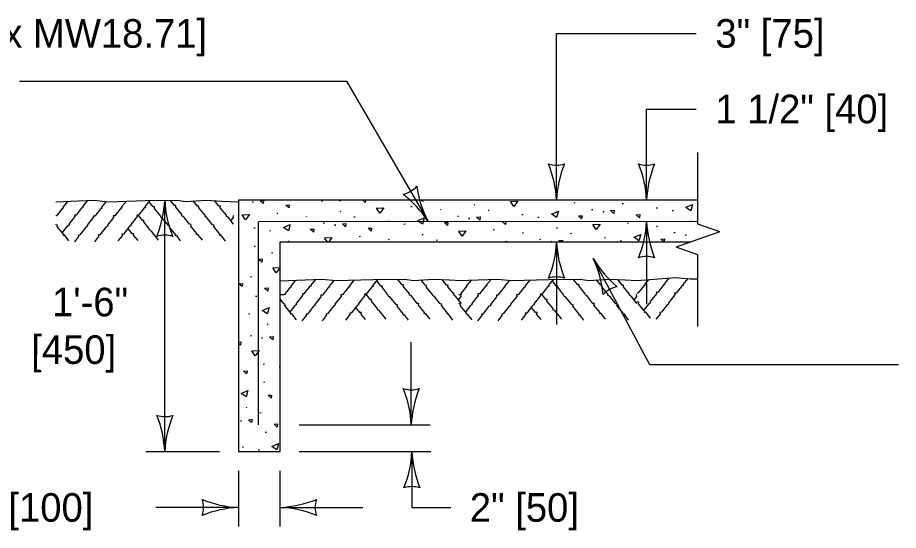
# Model space of a CAD drawing. Extents: x 49991.4 to 50021, y 49987.6 to 50011.4.
# Drawn here: x 50000.874 to 50002.724, y 49992.754 to 49993.83 of the extents above; entities that cross this region are included whole.
import ezdxf

# ---------------------------------------------------------------- set-up
doc = ezdxf.new("R2010")
doc.units = 0
for name, color, linetype in [('Level 1', 7, 'Continuous'), ('Level 2', 7, 'Continuous'), ('Level 3', 7, 'Continuous'), ('Level 6', 7, 'Continuous')]:
    doc.layers.add(name, color=color, linetype=linetype)

msp = doc.modelspace()

# ---------------------------------------------------------------- linework, layer by layer
at = {"layer": 'Level 1'}
for p, q in [((50002.3025, 49993.4474), (50001.3374, 49993.4474)), ((50001.3374, 49993.4474), (50001.3374, 49992.9196)), ((50001.3677, 49993.4446), (50001.3668, 49993.443)), ((50001.3677, 49993.4434), (50001.3668, 49993.4417)), ((50001.5118, 49993.4459), (50001.5144, 49993.4462)), ((50001.8343, 49993.4381), (50001.8325, 49993.4366)), ((50002.0436, 49993.4422), (50002.0428, 49993.4405)), ((50002.1434, 49993.4402), (50002.1461, 49993.4405)), ((50001.4179, 49993.4201), (50001.4205, 49993.4203)), ((50001.5527, 49993.424), (50001.5508, 49993.4226)), ((50001.6996, 49993.434), (50001.7022, 49993.4343)), ((50001.762, 49993.4281), (50001.7611, 49993.4264)), ((50001.8617, 49993.4262), (50001.8644, 49993.4264)), ((50002.079, 49993.4278), (50002.0815, 49993.4281)), ((50002.104, 49993.424), (50002.1033, 49993.4224)), ((50002.104, 49993.4228), (50002.1033, 49993.4212)), ((50002.2147, 49993.4312), (50002.2174, 49993.4314)), ((50002.2482, 49993.4254), (50002.2509, 49993.4256)), ((50002.3025, 49993.4028), (50001.3798, 49993.4022)), ((50001.3798, 49992.9758), (50001.3798, 49993.4022)), ((50001.4802, 49993.4141), (50001.4794, 49993.4124)), ((50001.58, 49993.4122), (50001.5826, 49993.4124)), ((50001.6513, 49993.4031), (50001.6539, 49993.4034)), ((50001.7973, 49993.4138), (50001.7999, 49993.4141)), ((50001.8224, 49993.41), (50001.8216, 49993.4083)), ((50001.8224, 49993.4087), (50001.8216, 49993.407)), ((50001.933, 49993.4171), (50001.9356, 49993.4173)), ((50001.9666, 49993.4114), (50001.9692, 49993.4116)), ((50002.2891, 49993.4035), (50002.2871, 49993.402)), ((50001.3696, 49993.389), (50001.3723, 49993.3893)), ((50001.4031, 49993.3832), (50001.4058, 49993.3834)), ((50001.5156, 49993.3997), (50001.5182, 49993.3999)), ((50001.5407, 49993.396), (50001.5399, 49993.3942)), ((50001.5407, 49993.3948), (50001.5399, 49993.3929)), ((50001.6848, 49993.3973), (50001.6875, 49993.3975)), ((50001.8726, 49993.3853), (50001.8752, 49993.3855)), ((50002.0074, 49993.3894), (50002.0054, 49993.388)), ((50002.1543, 49993.3994), (50002.157, 49993.3997)), ((50002.2166, 49993.3936), (50002.2158, 49993.3917)), ((50001.5909, 49993.3712), (50001.5935, 49993.3716)), ((50001.6533, 49993.3654), (50001.6524, 49993.3636)), ((50001.7258, 49993.3754), (50001.7237, 49993.374)), ((50001.753, 49993.3634), (50001.7557, 49993.3638)), ((50001.9349, 49993.3795), (50001.9341, 49993.3777)), ((50001.9703, 49993.3651), (50001.9728, 49993.3654)), ((50002.0348, 49993.3775), (50002.0374, 49993.3778)), ((50002.106, 49993.3684), (50002.1087, 49993.3687)), ((50002.1396, 49993.3626), (50002.1422, 49993.363)), ((50002.2519, 49993.3792), (50002.2545, 49993.3794)), ((50002.2771, 49993.3754), (50002.2761, 49993.3735)), ((50002.2771, 49993.3741), (50002.2763, 49993.3723)), ((50001.3716, 49993.3513), (50001.3707, 49993.3496)), ((50001.4252, 49992.9196), (50001.4252, 49993.3596)), ((50001.4252, 49993.3596), (50002.2875, 49993.3596)), ((50001.444, 49993.3613), (50001.4421, 49993.3599)), ((50001.9954, 49993.3613), (50001.9946, 49993.3596)), ((50001.9954, 49993.36), (50001.9952, 49993.3596)), ((50001.4069, 49993.337), (50001.4095, 49993.3372)), ((50001.3628, 49993.2866), (50001.3654, 49993.287)), ((50001.3736, 49993.2458), (50001.3763, 49993.246)), ((50001.3588, 49993.209), (50001.3613, 49993.2094)), ((50001.3996, 49993.1871), (50001.3976, 49993.1857)), ((50001.3624, 49993.1628), (50001.3652, 49993.163)), ((50001.3876, 49993.159), (50001.3868, 49993.1574)), ((50001.3876, 49993.1578), (50001.3868, 49993.156)), ((50001.3897, 49993.1034), (50001.3924, 49993.1037)), ((50001.4232, 49993.0976), (50001.4252, 49993.0978)), ((50001.3917, 49993.0658), (50001.3907, 49993.064)), ((50001.3554, 49993.013), (50001.3534, 49993.0115)), ((50001.3827, 49993.001), (50001.3853, 49993.0014)), ((50001.3434, 49992.9849), (50001.3425, 49992.9832)), ((50001.3434, 49992.9836), (50001.3425, 49992.9819)), ((50001.3936, 49992.9603), (50001.3962, 49992.9605)), ((50001.3374, 49992.9196), (50001.4252, 49992.9196)), ((50001.3453, 49992.9292), (50001.3479, 49992.9295)), ((50001.3788, 49992.9234), (50001.3815, 49992.9236))]:
    msp.add_line(p, q, dxfattribs=at)
for points in [[(50000.9537, 49993.4442), (50001.0341, 49993.4475), (50001.0647, 49993.4442), (50001.1425, 49993.447), (50001.2082, 49993.4474), (50001.2268, 49993.4447), (50001.2694, 49993.4477), (50001.3024, 49993.4456), (50001.3374, 49993.4436)], [(50000.9793, 49993.4453), (50000.9692, 49993.4333), (50000.9704, 49993.4305), (50000.9682, 49993.4305), (50000.9553, 49993.4144), (50000.9537, 49993.4144)], [(50001.0205, 49993.4469), (50001.011, 49993.4349), (50001.0124, 49993.4324), (50001.0096, 49993.4324), (50000.9969, 49993.416), (50000.9935, 49993.416), (50000.9939, 49993.4132), (50000.9811, 49993.3969), (50000.9811, 49993.3936), (50000.978, 49993.3925), (50000.9676, 49993.3793)], [(50001.0592, 49993.4442), (50001.0497, 49993.4325), (50001.0507, 49993.4301), (50001.0484, 49993.4301), (50001.0357, 49993.4138), (50001.0324, 49993.4138), (50001.0326, 49993.4107), (50001.0198, 49993.3946), (50001.0198, 49993.3914), (50001.0168, 49993.3905), (50001.0045, 49993.3743), (50001.0013, 49993.3738), (50001.0016, 49993.371), (50000.9929, 49993.3598)], [(50001.1023, 49993.4455), (50001.092, 49993.4333), (50001.0929, 49993.4305), (50001.0907, 49993.4305), (50001.078, 49993.4144), (50001.0747, 49993.4144), (50001.0748, 49993.411), (50001.0624, 49993.3949), (50001.0624, 49993.3922), (50001.0588, 49993.3909), (50001.0464, 49993.3748), (50001.0434, 49993.3744), (50001.0438, 49993.3712), (50001.0352, 49993.3602)], [(50001.1513, 49993.447), (50001.1417, 49993.4349), (50001.1425, 49993.4322), (50001.1403, 49993.4322), (50001.1275, 49993.416), (50001.1242, 49993.416), (50001.1247, 49993.413), (50001.1114, 49993.3963), (50001.1114, 49993.3934), (50001.1086, 49993.3925), (50001.096, 49993.3762), (50001.0929, 49993.3758), (50001.0937, 49993.373), (50001.0845, 49993.3617)], [(50001.2159, 49993.3617), (50001.2078, 49993.3729), (50001.2051, 49993.3728), (50001.2057, 49993.3744), (50001.1928, 49993.3906), (50001.1937, 49993.3936), (50001.1904, 49993.3944), (50001.1774, 49993.4106), (50001.1746, 49993.411), (50001.1743, 49993.4139), (50001.1614, 49993.4301), (50001.1615, 49993.4333), (50001.1585, 49993.4333), (50001.1495, 49993.4448)], [(50001.2618, 49993.3632), (50001.2521, 49993.3754), (50001.2497, 49993.3749), (50001.2502, 49993.3771), (50001.2372, 49993.3931), (50001.2384, 49993.3963), (50001.2347, 49993.3969), (50001.2221, 49993.4134), (50001.2189, 49993.4138), (50001.2189, 49993.417), (50001.2057, 49993.4328), (50001.2062, 49993.4359), (50001.2029, 49993.4359), (50001.194, 49993.4473)], [(50001.3102, 49993.3616), (50001.3007, 49993.3743), (50001.2982, 49993.3735), (50001.2984, 49993.3758), (50001.2855, 49993.3922), (50001.2868, 49993.3951), (50001.2833, 49993.3958), (50001.2702, 49993.4118), (50001.2674, 49993.4129), (50001.2674, 49993.4158), (50001.2541, 49993.4314), (50001.2546, 49993.4349), (50001.2517, 49993.4349), (50001.2424, 49993.4457)], [(50001.3274, 49993.3969), (50001.3157, 49993.412), (50001.3124, 49993.413), (50001.3122, 49993.416), (50001.2991, 49993.4316), (50001.2995, 49993.4349), (50001.2964, 49993.4349), (50001.2875, 49993.4465)], [(50001.3829, 49993.4462), (50001.3903, 49993.4469), (50001.3895, 49993.4401), (50001.3829, 49993.4462)], [(50001.4368, 49993.437), (50001.4442, 49993.4376), (50001.4434, 49993.431), (50001.4368, 49993.437)], [(50001.5516, 49993.4474), (50001.5511, 49993.4456), (50001.5486, 49993.4474)], [(50001.6041, 49993.4474), (50001.6037, 49993.4428), (50001.5987, 49993.4474)], [(50001.7253, 49993.4474), (50001.7251, 49993.4449), (50001.7225, 49993.4474)], [(50001.9087, 49993.4448), (50001.9242, 49993.4455), (50001.9161, 49993.4343), (50001.9088, 49993.4447)], [(50002.2769, 49993.4324), (50002.2913, 49993.4383), (50002.2874, 49993.425), (50002.2771, 49993.4323)], [(50001.627, 49993.4308), (50001.6425, 49993.4314), (50001.6344, 49993.4203), (50001.6271, 49993.4305)], [(50001.9952, 49993.4183), (50002.0096, 49993.4242), (50002.0057, 49993.4109), (50001.9954, 49993.4182)], [(50002.1192, 49993.4257), (50002.1267, 49993.4262), (50002.1258, 49993.4195), (50002.1192, 49993.4257)], [(50001.1698, 49993.3636), (50001.1548, 49993.3821), (50001.1521, 49993.3828), (50001.1513, 49993.3856), (50001.1387, 49993.4017), (50001.1389, 49993.4048), (50001.1358, 49993.4049), (50001.1274, 49993.416)], [(50001.3274, 49993.4144), (50001.3261, 49993.4144), (50001.3266, 49993.411), (50001.3212, 49993.405)], [(50001.3453, 49993.4168), (50001.3608, 49993.4173), (50001.3526, 49993.4062), (50001.3454, 49993.4166)], [(50001.7136, 49993.4043), (50001.7278, 49993.4101), (50001.7241, 49993.397), (50001.7138, 49993.4042)], [(50001.77, 49993.4002), (50001.7774, 49993.4008), (50001.7767, 49993.3941), (50001.77, 49993.4002)], [(50001.8375, 49993.4117), (50001.845, 49993.4122), (50001.8442, 49993.4056), (50001.8375, 49993.4117)], [(50001.8915, 49993.4024), (50001.8989, 49993.403), (50001.8981, 49993.3963), (50001.8915, 49993.4024)], [(50002.0517, 49993.4142), (50002.0591, 49993.4148), (50002.0582, 49993.4082), (50002.0517, 49993.4142)], [(50002.1731, 49993.4164), (50002.1806, 49993.417), (50002.1797, 49993.4104), (50002.1731, 49993.4164)], [(50000.9813, 49993.3621), (50000.9723, 49993.3744), (50000.9692, 49993.3735), (50000.9698, 49993.3762), (50000.9571, 49993.3924), (50000.9578, 49993.3951), (50000.9547, 49993.3958), (50000.9537, 49993.3969)], [(50001.1268, 49993.3626), (50001.1172, 49993.3738), (50001.1176, 49993.377), (50001.1144, 49993.377), (50001.1055, 49993.3887)], [(50001.4318, 49993.3903), (50001.4462, 49993.3961), (50001.4425, 49993.3828), (50001.4321, 49993.3902)], [(50001.4883, 49993.3862), (50001.4958, 49993.3867), (50001.495, 49993.3801), (50001.4883, 49993.3862)], [(50001.5558, 49993.3975), (50001.5633, 49993.3982), (50001.5625, 49993.3915), (50001.5558, 49993.3975)], [(50001.6098, 49993.3883), (50001.6172, 49993.3889), (50001.6164, 49993.3821), (50001.6098, 49993.3883)], [(50001.7999, 49993.3821), (50001.8154, 49993.3828), (50001.8073, 49993.3716), (50001.8001, 49993.3819)], [(50002.0816, 49993.3962), (50002.097, 49993.3969), (50002.089, 49993.3855), (50002.0817, 49993.396)], [(50001.5183, 49993.3682), (50001.5338, 49993.3687), (50001.5272, 49993.3596)], [(50001.5242, 49993.3596), (50001.5184, 49993.3679)], [(50002.0106, 49993.363), (50002.018, 49993.3635), (50002.0176, 49993.3596)], [(50002.0143, 49993.3596), (50002.0106, 49993.363)], [(50002.1682, 49993.3697), (50002.1826, 49993.3755), (50002.1787, 49993.3622), (50002.1685, 49993.3695)], [(50002.2247, 49993.3656), (50002.2321, 49993.3662), (50002.2312, 49993.3596)], [(50002.2311, 49993.3596), (50002.2247, 49993.3656)], [(50001.896, 49993.3596), (50001.9009, 49993.3614), (50001.9003, 49993.3596)], [(50001.3374, 49993.3333), (50001.3376, 49993.3334), (50001.3374, 49993.3325)], [(50001.3797, 49993.3235), (50001.3871, 49993.3239), (50001.3863, 49993.3173), (50001.3797, 49993.3235)], [(50001.4095, 49993.3053), (50001.425, 49993.3059), (50001.4169, 49993.2948), (50001.4097, 49993.3051)], [(50001.3386, 49993.272), (50001.346, 49993.2727), (50001.3452, 49993.266), (50001.3386, 49993.272)], [(50001.4252, 49993.2783), (50001.5127, 49993.2817), (50001.5427, 49993.2786), (50001.6207, 49993.2807), (50001.6865, 49993.2814), (50001.7048, 49993.2787), (50001.7475, 49993.2817), (50001.7804, 49993.2799), (50001.8058, 49993.2786)], [(50001.4575, 49993.2793), (50001.4474, 49993.2672), (50001.4484, 49993.2645), (50001.4462, 49993.2645), (50001.4333, 49993.2487), (50001.4252, 49993.2487)], [(50001.4992, 49993.2812), (50001.4893, 49993.2689), (50001.4899, 49993.2666), (50001.4877, 49993.2666), (50001.4751, 49993.2506), (50001.4719, 49993.2506), (50001.472, 49993.2476), (50001.459, 49993.2306), (50001.459, 49993.2278), (50001.456, 49993.2266), (50001.4459, 49993.2134)], [(50001.5373, 49993.2781), (50001.5278, 49993.2668), (50001.5289, 49993.2645), (50001.5263, 49993.2645), (50001.5138, 49993.2479), (50001.5106, 49993.2479), (50001.5108, 49993.2446), (50001.4978, 49993.2286), (50001.4978, 49993.2255), (50001.4949, 49993.2246), (50001.4826, 49993.2082), (50001.4794, 49993.2082), (50001.4797, 49993.2052), (50001.4708, 49993.194)], [(50001.5799, 49993.2793), (50001.5701, 49993.2672), (50001.5713, 49993.2645), (50001.5686, 49993.2645), (50001.5558, 49993.2487), (50001.5528, 49993.2487), (50001.553, 49993.2455), (50001.5401, 49993.229), (50001.5401, 49993.226), (50001.5371, 49993.2248), (50001.5246, 49993.2088), (50001.5217, 49993.2084), (50001.5218, 49993.2055), (50001.5132, 49993.1941)], [(50001.6297, 49993.2807), (50001.6197, 49993.2687), (50001.6206, 49993.266), (50001.6184, 49993.266), (50001.6055, 49993.2503), (50001.6024, 49993.2503), (50001.6028, 49993.2474), (50001.5898, 49993.2304), (50001.5898, 49993.2276), (50001.5868, 49993.2266), (50001.5742, 49993.2101), (50001.5713, 49993.21), (50001.5715, 49993.2071), (50001.5625, 49993.1956)], [(50001.6944, 49993.1956), (50001.6863, 49993.2068), (50001.6834, 49993.2061), (50001.6842, 49993.2084), (50001.6705, 49993.2247), (50001.6718, 49993.2278), (50001.6687, 49993.2283), (50001.6555, 49993.2445), (50001.6528, 49993.2454), (50001.6522, 49993.2481), (50001.6394, 49993.2645), (50001.6398, 49993.2672), (50001.6367, 49993.2672), (50001.6282, 49993.2787)], [(50001.74, 49993.1973), (50001.7302, 49993.2094), (50001.7278, 49993.2089), (50001.7283, 49993.2113), (50001.7153, 49993.227), (50001.7161, 49993.2304), (50001.7131, 49993.2306), (50001.7001, 49993.2476), (50001.697, 49993.2479), (50001.6967, 49993.2509), (50001.6837, 49993.2668), (50001.6842, 49993.27), (50001.681, 49993.27), (50001.6724, 49993.2812)], [(50001.7881, 49993.1956), (50001.7787, 49993.2082), (50001.7765, 49993.2078), (50001.7766, 49993.2099), (50001.7637, 49993.226), (50001.7644, 49993.2292), (50001.7614, 49993.2296), (50001.7485, 49993.2458), (50001.7456, 49993.2469), (50001.745, 49993.2496), (50001.7321, 49993.2655), (50001.7326, 49993.2684), (50001.7296, 49993.2687), (50001.721, 49993.28)], [(50001.8058, 49993.2306), (50001.7937, 49993.246), (50001.7906, 49993.247), (50001.7903, 49993.2499), (50001.777, 49993.2656), (50001.7779, 49993.2687), (50001.7746, 49993.2689), (50001.7655, 49993.2807)], [(50001.8007, 49993.2786), (50001.8813, 49993.2817), (50001.9116, 49993.2786), (50001.9895, 49993.2807), (50002.0555, 49993.2814), (50002.0735, 49993.2787), (50002.1163, 49993.2817), (50002.1495, 49993.2799), (50002.1742, 49993.2786)], [(50001.8265, 49993.2793), (50001.8158, 49993.2672), (50001.8173, 49993.2645), (50001.8152, 49993.2645), (50001.8022, 49993.2487), (50001.8007, 49993.2487)], [(50001.868, 49993.2812), (50001.8578, 49993.2689), (50001.8592, 49993.2666), (50001.8564, 49993.2666), (50001.8439, 49993.2506), (50001.8405, 49993.2506), (50001.8408, 49993.2476), (50001.828, 49993.2306), (50001.828, 49993.2278), (50001.825, 49993.2266), (50001.8148, 49993.2134)], [(50001.9058, 49993.2781), (50001.8966, 49993.2668), (50001.8976, 49993.2645), (50001.8953, 49993.2645), (50001.8826, 49993.2479), (50001.8792, 49993.2479), (50001.8798, 49993.2446), (50001.8667, 49993.2286), (50001.8667, 49993.2255), (50001.8637, 49993.2246), (50001.851, 49993.2082), (50001.8483, 49993.2082), (50001.8486, 49993.2052), (50001.8395, 49993.194)], [(50001.9492, 49993.2793), (50001.9388, 49993.2672), (50001.94, 49993.2645), (50001.9376, 49993.2645), (50001.9249, 49993.2487), (50001.9214, 49993.2487), (50001.9222, 49993.2455), (50001.909, 49993.229), (50001.909, 49993.226), (50001.9058, 49993.2248), (50001.8934, 49993.2088), (50001.8904, 49993.2084), (50001.8909, 49993.2055), (50001.882, 49993.1941)], [(50001.9988, 49993.2807), (50001.9886, 49993.2687), (50001.9895, 49993.266), (50001.9871, 49993.266), (50001.9745, 49993.2503), (50001.9711, 49993.2503), (50001.9716, 49993.2474), (50001.9584, 49993.2304), (50001.9584, 49993.2276), (50001.9553, 49993.2266), (50001.9431, 49993.2101), (50001.94, 49993.21), (50001.9406, 49993.2071), (50001.9315, 49993.1956)], [(50002.063, 49993.1956), (50002.0548, 49993.2068), (50002.0524, 49993.2061), (50002.0529, 49993.2084), (50002.0398, 49993.2247), (50002.0408, 49993.2278), (50002.0376, 49993.2283), (50002.0243, 49993.2445), (50002.0213, 49993.2454), (50002.0212, 49993.2481), (50002.0081, 49993.2645), (50002.0085, 49993.2672), (50002.0057, 49993.2672), (50001.9964, 49993.2787)], [(50002.1087, 49993.1973), (50002.0991, 49993.2094), (50002.0967, 49993.2089), (50002.0969, 49993.2113), (50002.0841, 49993.227), (50002.0851, 49993.2304), (50002.0819, 49993.2306), (50002.069, 49993.2476), (50002.0662, 49993.2479), (50002.0658, 49993.2509), (50002.0529, 49993.2668), (50002.0531, 49993.27), (50002.0503, 49993.27), (50002.0411, 49993.2812)], [(50002.157, 49993.1956), (50002.148, 49993.2082), (50002.1451, 49993.2078), (50002.1452, 49993.2099), (50002.1325, 49993.226), (50002.1335, 49993.2292), (50002.1304, 49993.2296), (50002.1172, 49993.2458), (50002.1143, 49993.2469), (50002.1143, 49993.2496), (50002.1009, 49993.2655), (50002.1014, 49993.2684), (50002.0984, 49993.2687), (50002.0894, 49993.28)], [(50002.1742, 49993.2306), (50002.1626, 49993.246), (50002.1592, 49993.247), (50002.1589, 49993.2499), (50002.1462, 49993.2656), (50002.1465, 49993.2687), (50002.1434, 49993.2689), (50002.1343, 49993.2807)], [(50002.1742, 49993.2786), (50002.2553, 49993.2851), (50002.2861, 49993.2822), (50002.3025, 49993.2824)], [(50002.1989, 49993.2806), (50002.1905, 49993.2705), (50002.1917, 49993.2683), (50002.1893, 49993.2683), (50002.1763, 49993.252), (50002.1748, 49993.252)], [(50002.2415, 49993.284), (50002.232, 49993.2726), (50002.2333, 49993.2701), (50002.2311, 49993.2701), (50002.2183, 49993.2535), (50002.215, 49993.2535), (50002.2155, 49993.2508), (50002.202, 49993.2347), (50002.202, 49993.2314), (50002.1994, 49993.2301), (50002.1892, 49993.2171)], [(50002.2813, 49993.2827), (50002.2709, 49993.2701), (50002.2721, 49993.268), (50002.2694, 49993.268), (50002.257, 49993.2519), (50002.2534, 49993.2519), (50002.2541, 49993.2487), (50002.2407, 49993.2319), (50002.2407, 49993.229), (50002.238, 49993.2279), (50002.2257, 49993.212), (50002.2225, 49993.2115), (50002.2231, 49993.2084), (50002.2142, 49993.1976)], [(50001.3925, 49993.2629), (50001.3998, 49993.2634), (50001.3991, 49993.2567), (50001.3925, 49993.2629)], [(50001.4592, 49993.1962), (50001.45, 49993.2084), (50001.4474, 49993.2079), (50001.4476, 49993.2101), (50001.4348, 49993.2264), (50001.4357, 49993.2293), (50001.4325, 49993.2296), (50001.4252, 49993.24)], [(50001.6478, 49993.1974), (50001.6329, 49993.216), (50001.6302, 49993.2168), (50001.6297, 49993.2198), (50001.6168, 49993.2353), (50001.6171, 49993.2389), (50001.614, 49993.239), (50001.6054, 49993.2499)], [(50001.8058, 49993.2487), (50001.8041, 49993.2487), (50001.8044, 49993.2455), (50001.7996, 49993.2391)], [(50002.0166, 49993.1974), (50002.0019, 49993.216), (50001.9988, 49993.2168), (50001.9988, 49993.2198), (50001.9855, 49993.2353), (50001.9861, 49993.2389), (50001.9828, 49993.239), (50001.9744, 49993.2499)], [(50002.1742, 49993.2487), (50002.173, 49993.2487), (50002.1734, 49993.2455), (50002.1683, 49993.2391)], [(50002.2027, 49993.1997), (50002.1932, 49993.2121), (50002.1905, 49993.2113), (50002.1912, 49993.2138), (50002.178, 49993.2301), (50002.1787, 49993.2332), (50002.1759, 49993.2333), (50002.1748, 49993.2347)], [(50001.3875, 49993.2161), (50001.4019, 49993.222), (50001.3981, 49993.2086), (50001.3877, 49993.2159)], [(50001.6046, 49993.1967), (50001.5953, 49993.2082), (50001.5957, 49993.2113), (50001.5923, 49993.2113), (50001.5835, 49993.2228)], [(50001.8286, 49993.1962), (50001.8189, 49993.2084), (50001.8158, 49993.2079), (50001.8168, 49993.2101), (50001.8035, 49993.2264), (50001.8046, 49993.2293), (50001.8017, 49993.2296), (50001.8007, 49993.2306)], [(50001.9734, 49993.1967), (50001.9638, 49993.2082), (50001.9648, 49993.2113), (50001.9613, 49993.2113), (50001.9522, 49993.2228)], [(50001.4029, 49993.1606), (50001.4103, 49993.1612), (50001.4095, 49993.1545), (50001.4029, 49993.1606)], [(50001.3374, 49993.1494), (50001.3427, 49993.1498), (50001.3419, 49993.1432), (50001.3374, 49993.1474)], [(50001.3653, 49993.1312), (50001.3807, 49993.1318), (50001.3727, 49993.1205), (50001.3654, 49993.131)], [(50001.3481, 49993.0886), (50001.3556, 49993.0892), (50001.3547, 49993.0826), (50001.3481, 49993.0886)], [(50001.3433, 49993.0419), (50001.3575, 49993.0477), (50001.3537, 49993.0345), (50001.3434, 49993.0418)], [(50001.3996, 49993.0378), (50001.407, 49993.0384), (50001.4063, 49993.0318), (50001.3996, 49993.0378)], [(50001.3586, 49992.9864), (50001.366, 49992.9871), (50001.3652, 49992.9804), (50001.3586, 49992.9864)], [(50001.4125, 49992.9772), (50001.4198, 49992.9778), (50001.4191, 49992.9712), (50001.4125, 49992.9772)], [(50001.4075, 49992.9305), (50001.4218, 49992.9363), (50001.4181, 49992.9231), (50001.4078, 49992.9304)]]:
    msp.add_lwpolyline(points, dxfattribs=at)
at = {"layer": 'Level 3'}
for p, q in [((50002.0055, 49993.4474), (50002.0055, 49993.7973)), ((50002.0055, 49993.7973), (50002.2991, 49993.7973)), ((50000.8775, 49993.6973), (50001.5645, 49993.6973)), ((50001.5645, 49993.6973), (50001.7359, 49993.4024)), ((50002.1947, 49993.4474), (50002.1947, 49993.6387)), ((50002.1947, 49993.6387), (50002.2991, 49993.6387)), ((50001.1828, 49992.9196), (50001.1828, 49993.4472)), ((50002.1947, 49993.4027), (50002.1947, 49993.2293)), ((50002.0055, 49993.3596), (50002.0055, 49993.1862)), ((50002.2013, 49993.1018), (50002.0826, 49993.3247)), ((50001.7005, 49992.9758), (50001.7005, 49993.1492)), ((50002.7235, 49993.1018), (50002.2013, 49993.1018)), ((50001.4652, 49992.9758), (50001.7405, 49992.9758)), ((50001.1428, 49992.9196), (50001.2974, 49992.9196)), ((50001.4652, 49992.9196), (50001.7418, 49992.9196)), ((50001.7018, 49992.9196), (50001.7018, 49992.8024)), ((50001.3374, 49992.8796), (50001.3374, 49992.7624)), ((50001.4252, 49992.7624), (50001.4252, 49992.8796)), ((50001.3374, 49992.8024), (50001.164, 49992.8024)), ((50001.4252, 49992.8024), (50001.5986, 49992.8024)), ((50001.7018, 49992.8024), (50001.7834, 49992.8024))]:
    msp.add_line(p, q, dxfattribs=at)
for centre, radius, start, end in [((50002.0055, 49993.5756), 0.0548, 252.1388, 287.8612), ((50001.7728, 49993.4359), 0.233, 2.8273, 22.0772), ((50002.2276, 49993.4382), 0.2223, 157.456, 177.6395), ((50002.1947, 49993.5756), 0.0548, 252.1388, 287.8612), ((50001.962, 49993.4359), 0.233, 2.8273, 22.0772), ((50002.4168, 49993.4382), 0.2223, 157.456, 177.6395), ((50001.6715, 49993.5133), 0.0548, 282.3148, 318.0371), ((50001.9326, 49993.5062), 0.2223, 187.632, 207.8155), ((50001.5405, 49993.2755), 0.233, 33.0033, 52.2531), ((50000.9607, 49993.457), 0.2223, 337.3034, 357.4869), ((50001.4155, 49993.4581), 0.233, 182.6747, 201.9245), ((50001.9726, 49993.4119), 0.2223, 337.456, 357.6395), ((50002.4274, 49993.4142), 0.233, 182.8273, 202.0772), ((50001.1825, 49993.319), 0.0548, 71.9862, 107.7085), ((50001.7834, 49993.3688), 0.2223, 337.456, 357.6395), ((50002.2382, 49993.3711), 0.233, 182.8273, 202.0772), ((50002.1947, 49993.2745), 0.0548, 72.1388, 107.8612), ((50001.8822, 49993.2283), 0.2223, 5.5018, 25.6853), ((50002.2826, 49993.4443), 0.233, 210.8731, 230.123), ((50002.0055, 49993.2314), 0.0548, 72.1388, 107.8612), ((50002.1429, 49993.2115), 0.0548, 100.1846, 135.907), ((50001.7005, 49993.104), 0.0548, 252.1388, 287.8612), ((50001.4678, 49992.9643), 0.233, 2.8273, 22.0772), ((50001.9226, 49992.9666), 0.2223, 157.456, 177.6395), ((50001.1831, 49993.0478), 0.0548, 251.9862, 287.7085), ((50000.9501, 49992.9087), 0.233, 2.6747, 21.9245), ((50001.4049, 49992.9099), 0.2223, 157.3034, 177.4869), ((50001.4797, 49992.9288), 0.2223, 337.456, 357.6395), ((50001.9345, 49992.9311), 0.233, 182.8273, 202.0772), ((50001.7018, 49992.7914), 0.0548, 72.1388, 107.8612), ((50001.3466, 49993.0245), 0.2223, 247.456, 267.6395), ((50001.2092, 49992.8024), 0.0548, 342.1388, 17.8612), ((50001.4137, 49993.0351), 0.233, 272.8273, 292.0772), ((50001.5534, 49992.8024), 0.0548, 162.1388, 197.8612), ((50001.3489, 49992.5697), 0.233, 92.8273, 112.0772), ((50001.416, 49992.5803), 0.2223, 67.456, 87.6395)]:
    msp.add_arc(centre, radius, start, end, dxfattribs=at)
at = {"layer": 'Level 6'}
for p, q in [((50002.3025, 49993.3973), (50002.3025, 49993.5474)), ((50002.3482, 49993.3811), (50002.3025, 49993.3973)), ((50002.3025, 49993.3649), (50002.2568, 49993.3487)), ((50002.3482, 49993.3811), (50002.3025, 49993.3649)), ((50002.3025, 49993.3325), (50002.2568, 49993.3487)), ((50002.3025, 49993.1824), (50002.3025, 49993.3325))]:
    msp.add_line(p, q, dxfattribs=at)

# ---------------------------------------------------------------- texts
at = {"layer": 'Level 2'}
for s, p in [('[152.4 x 152.4 x MW18.71]', (50000.3128, 49993.7673)), ('3" [75]', (50002.3391, 49993.7673)), ('1 1/2" [40]', (50002.3391, 49993.6087)), ('4" [100]', (50000.759, 49992.7724)), ('2" [50]', (50001.8234, 49992.7724))]:
    msp.add_text(s, height=0.06, dxfattribs=at).set_placement(p)
for s, p in [('1\'-6"', (50000.9459, 49993.2038)), ('[450]', (50000.9022, 49993.1039))]:
    msp.add_text(s, height=0.06, rotation=359.8801, dxfattribs=at).set_placement(p)

doc.saveas('drawing.dxf')
